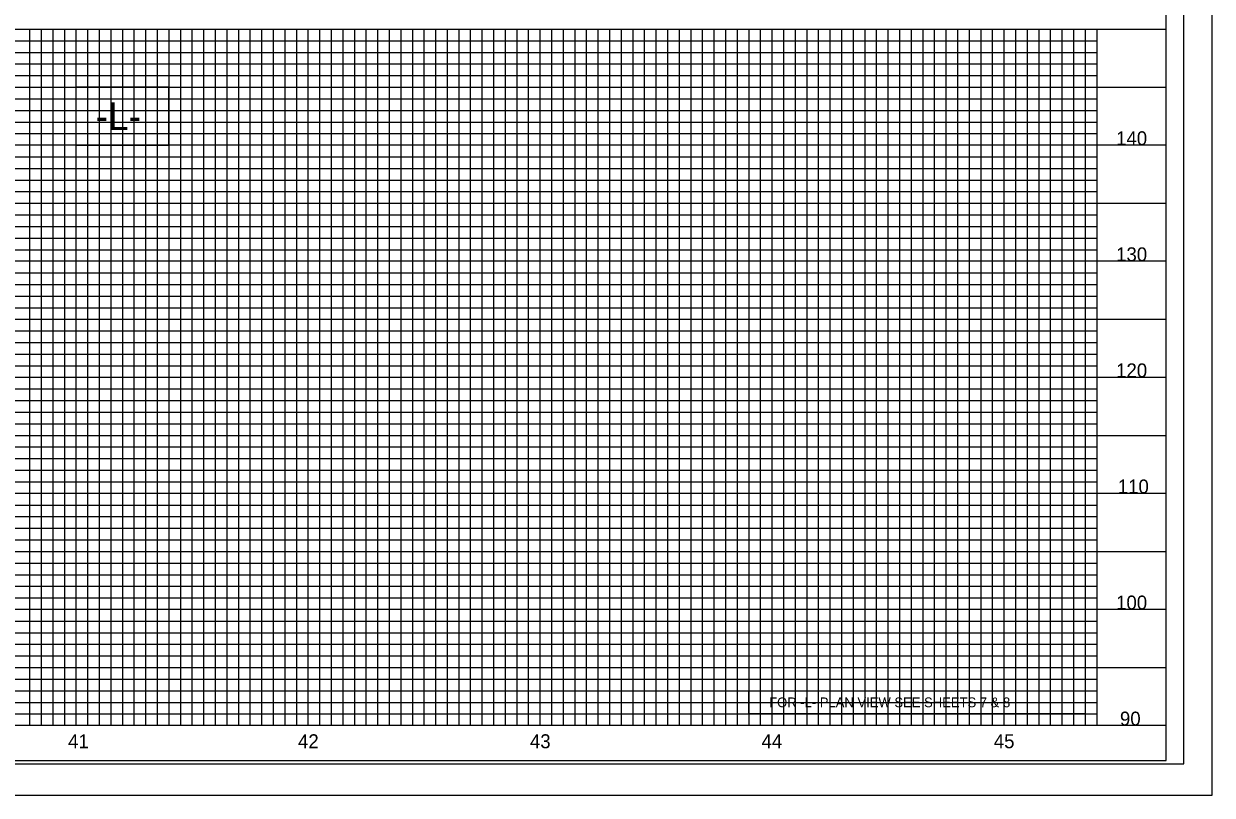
# Model space of a CAD drawing. Extents: x 2113763 to 2114783, y 714280 to 714940.
# Drawn here: x 2114270 to 2114783, y 714280 to 714613 of the extents above; entities that cross this region are included whole.
import ezdxf

# ---------------------------------------------------------------- set-up
doc = ezdxf.new("R2010")
doc.units = 0
for name, color, linetype in [('Exist Vertical Profile Horizontal Axis Label Major', 7, 'Continuous'), ('Exist Vertical Profile Vertical Axis Label', 7, 'Continuous'), ('Prop Grid Mask', 7, 'Continuous'), ('Prop PFL Text', 7, 'Continuous'), ('Sheet Cutting Line CELL', 7, 'Continuous'), ('Sheet Layout Profile Border Port 2', 7, 'Continuous'), ('Sheet Plot Border Inside CELL', 7, 'Continuous'), ('Sheet Plot Border Outside CELL', 7, 'Continuous'), ('Sheet Profile CELL', 7, 'Continuous'), ('Sheet Profile Grid Major CELL', 7, 'Continuous'), ('Sheet Profile Grid Middle CELL', 7, 'Continuous'), ('Sheet Profile Grid Minor CELL', 7, 'Continuous')]:
    doc.layers.add(name, color=color, linetype=linetype)

msp = doc.modelspace()

# ---------------------------------------------------------------- linework, layer by layer
at = {"layer": 'Exist Vertical Profile Vertical Axis Label'}
msp.add_lwpolyline([(2114582.76, 714325.29), (2114727.76, 714325.29), (2114727.76, 714315.29), (2114582.76, 714315.29)], close=True, dxfattribs=at)
at = {"layer": 'Prop Grid Mask'}
for points in [[(2114292.76, 714560.29), (2114332.76, 714560.29), (2114332.76, 714585.29), (2114292.76, 714585.29)], [(2114582.76, 714325.29), (2114727.76, 714325.29), (2114727.76, 714315.29), (2114582.76, 714315.29)]]:
    msp.add_lwpolyline(points, close=True, dxfattribs=at)
at = {"layer": 'Prop PFL Text'}
msp.add_lwpolyline([(2114292.76, 714560.29), (2114332.76, 714560.29), (2114332.76, 714585.29), (2114292.76, 714585.29)], close=True, dxfattribs=at)
at = {"layer": 'Sheet Cutting Line CELL'}
for p, q in [((2114782.56, 714280.29), (2114782.56, 714940.29)), ((2113762.56, 714280.29), (2114782.56, 714280.29))]:
    msp.add_line(p, q, dxfattribs=at)
at = {"layer": 'Sheet Layout Profile Border Port 2'}
msp.add_lwpolyline([(2113892.76, 714610.29), (2114732.76, 714610.29), (2114732.76, 714310.29), (2113892.76, 714310.29)], close=True, dxfattribs=at)
at = {"layer": 'Sheet Plot Border Inside CELL'}
msp.add_lwpolyline([(2113770.36, 714293.76), (2114770.26, 714293.76), (2114770.26, 714926.82), (2113770.36, 714926.82)], close=True, dxfattribs=at)
at = {"layer": 'Sheet Plot Border Outside CELL'}
msp.add_lwpolyline([(2113762.56, 714280.29), (2114782.56, 714280.29), (2114782.56, 714940.29), (2113762.56, 714940.29)], close=True, dxfattribs=at)
at = {"layer": 'Sheet Profile CELL'}
for p, q in [((2113862.76, 714610.29), (2114762.76, 714610.29)), ((2114762.76, 714310.29), (2113862.76, 714310.29)), ((2113862.76, 714295.29), (2114762.76, 714295.29))]:
    msp.add_line(p, q, dxfattribs=at)
msp.add_lwpolyline([(2114762.76, 714925.29), (2113862.76, 714925.29), (2113862.76, 714295.29), (2114762.76, 714295.29)], close=True, dxfattribs=at)
at = {"layer": 'Sheet Profile Grid Major CELL'}
for p, q in [((2114292.76, 714610.29), (2114292.76, 714310.29)), ((2114317.76, 714610.29), (2114317.76, 714310.29)), ((2114342.76, 714610.29), (2114342.76, 714310.29)), ((2114367.76, 714610.29), (2114367.76, 714310.29)), ((2114392.76, 714610.29), (2114392.76, 714310.29)), ((2114417.76, 714610.29), (2114417.76, 714310.29)), ((2114442.76, 714610.29), (2114442.76, 714310.29)), ((2114467.76, 714610.29), (2114467.76, 714310.29)), ((2114492.76, 714610.29), (2114492.76, 714310.29)), ((2114517.76, 714610.29), (2114517.76, 714310.29)), ((2114542.76, 714610.29), (2114542.76, 714310.29)), ((2114567.76, 714610.29), (2114567.76, 714310.29)), ((2114592.76, 714610.29), (2114592.76, 714310.29)), ((2114617.76, 714610.29), (2114617.76, 714310.29)), ((2114642.76, 714610.29), (2114642.76, 714310.29)), ((2114667.76, 714610.29), (2114667.76, 714310.29)), ((2114692.76, 714610.29), (2114692.76, 714310.29)), ((2114717.76, 714610.29), (2114717.76, 714310.29)), ((2114732.76, 714610.29), (2114732.76, 714310.29)), ((2113862.76, 714585.29), (2114762.76, 714585.29)), ((2114762.76, 714560.29), (2113862.76, 714560.29)), ((2113862.76, 714535.29), (2114762.76, 714535.29)), ((2114762.76, 714510.29), (2113862.76, 714510.29)), ((2113862.76, 714485.29), (2114762.76, 714485.29)), ((2114762.76, 714460.29), (2113862.76, 714460.29)), ((2113862.76, 714435.29), (2114762.76, 714435.29)), ((2114762.76, 714410.29), (2113862.76, 714410.29)), ((2113862.76, 714385.29), (2114762.76, 714385.29)), ((2114762.76, 714360.29), (2113862.76, 714360.29)), ((2113862.76, 714335.29), (2114762.76, 714335.29))]:
    msp.add_line(p, q, dxfattribs=at)
at = {"layer": 'Sheet Profile Grid Middle CELL'}
for p, q in [((2113892.76, 714605.29), (2114732.76, 714605.29)), ((2113892.76, 714600.29), (2114732.76, 714600.29)), ((2113892.76, 714595.29), (2114732.76, 714595.29)), ((2113892.76, 714590.29), (2114732.76, 714590.29)), ((2113892.76, 714580.29), (2114732.76, 714580.29)), ((2113892.76, 714575.29), (2114732.76, 714575.29)), ((2113892.76, 714570.29), (2114732.76, 714570.29)), ((2113892.76, 714565.29), (2114732.76, 714565.29)), ((2113892.76, 714555.29), (2114732.76, 714555.29)), ((2113892.76, 714550.29), (2114732.76, 714550.29)), ((2113892.76, 714545.29), (2114732.76, 714545.29)), ((2113892.76, 714540.29), (2114732.76, 714540.29)), ((2113892.76, 714530.29), (2114732.76, 714530.29)), ((2113892.76, 714525.29), (2114732.76, 714525.29)), ((2113892.76, 714520.29), (2114732.76, 714520.29)), ((2113892.76, 714515.29), (2114732.76, 714515.29)), ((2113892.76, 714505.29), (2114732.76, 714505.29)), ((2113892.76, 714500.29), (2114732.76, 714500.29)), ((2113892.76, 714495.29), (2114732.76, 714495.29)), ((2113892.76, 714490.29), (2114732.76, 714490.29)), ((2113892.76, 714480.29), (2114732.76, 714480.29)), ((2113892.76, 714475.29), (2114732.76, 714475.29)), ((2113892.76, 714470.29), (2114732.76, 714470.29)), ((2113892.76, 714465.29), (2114732.76, 714465.29)), ((2113892.76, 714455.29), (2114732.76, 714455.29)), ((2113892.76, 714450.29), (2114732.76, 714450.29)), ((2113892.76, 714445.29), (2114732.76, 714445.29)), ((2113892.76, 714440.29), (2114732.76, 714440.29)), ((2113892.76, 714430.29), (2114732.76, 714430.29)), ((2113892.76, 714425.29), (2114732.76, 714425.29)), ((2113892.76, 714420.29), (2114732.76, 714420.29)), ((2113892.76, 714415.29), (2114732.76, 714415.29)), ((2113892.76, 714405.29), (2114732.76, 714405.29)), ((2113892.76, 714400.29), (2114732.76, 714400.29)), ((2113892.76, 714395.29), (2114732.76, 714395.29)), ((2113892.76, 714390.29), (2114732.76, 714390.29)), ((2113892.76, 714380.29), (2114732.76, 714380.29)), ((2113892.76, 714375.29), (2114732.76, 714375.29)), ((2113892.76, 714370.29), (2114732.76, 714370.29)), ((2113892.76, 714365.29), (2114732.76, 714365.29)), ((2113892.76, 714355.29), (2114732.76, 714355.29)), ((2113892.76, 714350.29), (2114732.76, 714350.29)), ((2113892.76, 714345.29), (2114732.76, 714345.29)), ((2113892.76, 714340.29), (2114732.76, 714340.29)), ((2113892.76, 714330.29), (2114732.76, 714330.29)), ((2113892.76, 714325.29), (2114732.76, 714325.29)), ((2113892.76, 714320.29), (2114732.76, 714320.29)), ((2113892.76, 714315.29), (2114732.76, 714315.29))]:
    msp.add_line(p, q, dxfattribs=at)
msp.add_lwpolyline([(2114657.76, 714475.29), (2114732.76, 714475.29)], dxfattribs=at)
at = {"layer": 'Sheet Profile Grid Minor CELL'}
for p, q in [((2114272.76, 714610.29), (2114272.76, 714310.29)), ((2114277.76, 714610.29), (2114277.76, 714310.29)), ((2114282.76, 714610.29), (2114282.76, 714310.29)), ((2114287.76, 714610.29), (2114287.76, 714310.29)), ((2114297.76, 714610.29), (2114297.76, 714310.29)), ((2114302.76, 714610.29), (2114302.76, 714310.29)), ((2114307.76, 714610.29), (2114307.76, 714310.29)), ((2114312.76, 714610.29), (2114312.76, 714310.29)), ((2114322.76, 714610.29), (2114322.76, 714310.29)), ((2114327.76, 714610.29), (2114327.76, 714310.29)), ((2114332.76, 714610.29), (2114332.76, 714310.29)), ((2114337.76, 714610.29), (2114337.76, 714310.29)), ((2114347.76, 714610.29), (2114347.76, 714310.29)), ((2114352.76, 714610.29), (2114352.76, 714310.29)), ((2114357.76, 714610.29), (2114357.76, 714310.29)), ((2114362.76, 714610.29), (2114362.76, 714310.29)), ((2114372.76, 714610.29), (2114372.76, 714310.29)), ((2114377.76, 714610.29), (2114377.76, 714310.29)), ((2114382.76, 714610.29), (2114382.76, 714310.29)), ((2114387.76, 714610.29), (2114387.76, 714310.29)), ((2114397.76, 714610.29), (2114397.76, 714310.29)), ((2114402.76, 714610.29), (2114402.76, 714310.29)), ((2114407.76, 714610.29), (2114407.76, 714310.29)), ((2114412.76, 714610.29), (2114412.76, 714310.29)), ((2114422.76, 714610.29), (2114422.76, 714310.29)), ((2114427.76, 714610.29), (2114427.76, 714310.29)), ((2114432.76, 714610.29), (2114432.76, 714310.29)), ((2114437.76, 714610.29), (2114437.76, 714310.29)), ((2114447.76, 714610.29), (2114447.76, 714310.29)), ((2114452.76, 714610.29), (2114452.76, 714310.29)), ((2114457.76, 714610.29), (2114457.76, 714310.29)), ((2114462.76, 714610.29), (2114462.76, 714310.29)), ((2114472.76, 714610.29), (2114472.76, 714310.29)), ((2114477.76, 714610.29), (2114477.76, 714310.29)), ((2114482.76, 714610.29), (2114482.76, 714310.29)), ((2114487.76, 714610.29), (2114487.76, 714310.29)), ((2114497.76, 714610.29), (2114497.76, 714310.29)), ((2114502.76, 714610.29), (2114502.76, 714310.29)), ((2114507.76, 714610.29), (2114507.76, 714310.29)), ((2114512.76, 714610.29), (2114512.76, 714310.29)), ((2114522.76, 714610.29), (2114522.76, 714310.29)), ((2114527.76, 714610.29), (2114527.76, 714310.29)), ((2114532.76, 714610.29), (2114532.76, 714310.29)), ((2114537.76, 714610.29), (2114537.76, 714310.29)), ((2114547.76, 714610.29), (2114547.76, 714310.29)), ((2114552.76, 714610.29), (2114552.76, 714310.29)), ((2114557.76, 714610.29), (2114557.76, 714310.29)), ((2114562.76, 714610.29), (2114562.76, 714310.29)), ((2114572.76, 714610.29), (2114572.76, 714310.29)), ((2114577.76, 714610.29), (2114577.76, 714310.29)), ((2114582.76, 714610.29), (2114582.76, 714310.29)), ((2114587.76, 714610.29), (2114587.76, 714310.29)), ((2114597.76, 714610.29), (2114597.76, 714310.29)), ((2114602.76, 714610.29), (2114602.76, 714310.29)), ((2114607.76, 714610.29), (2114607.76, 714310.29)), ((2114612.76, 714610.29), (2114612.76, 714310.29)), ((2114622.76, 714610.29), (2114622.76, 714310.29)), ((2114627.76, 714610.29), (2114627.76, 714310.29)), ((2114632.76, 714610.29), (2114632.76, 714310.29)), ((2114637.76, 714610.29), (2114637.76, 714310.29)), ((2114647.76, 714610.29), (2114647.76, 714310.29)), ((2114652.76, 714610.29), (2114652.76, 714310.29)), ((2114657.76, 714610.29), (2114657.76, 714310.29)), ((2114662.76, 714610.29), (2114662.76, 714310.29)), ((2114672.76, 714610.29), (2114672.76, 714310.29)), ((2114677.76, 714610.29), (2114677.76, 714310.29)), ((2114682.76, 714610.29), (2114682.76, 714310.29)), ((2114687.76, 714610.29), (2114687.76, 714310.29)), ((2114697.76, 714610.29), (2114697.76, 714310.29)), ((2114702.76, 714610.29), (2114702.76, 714310.29)), ((2114707.76, 714610.29), (2114707.76, 714310.29)), ((2114712.76, 714610.29), (2114712.76, 714310.29)), ((2114722.76, 714610.29), (2114722.76, 714310.29)), ((2114727.76, 714610.29), (2114727.76, 714310.29))]:
    msp.add_line(p, q, dxfattribs=at)

# ---------------------------------------------------------------- texts
at = {"layer": 'Exist Vertical Profile Horizontal Axis Label Major'}
for s, p in [('41', (2114289.36, 714300.53)), ('42', (2114388.48, 714300.53)), ('43', (2114488.45, 714300.53)), ('44', (2114588.27, 714300.53)), ('45', (2114688.39, 714300.53))]:
    msp.add_text(s, height=6, dxfattribs=at).set_placement(p)
at = {"layer": 'Exist Vertical Profile Vertical Axis Label'}
for s, p in [('140', (2114741.12, 714560.29)), ('130', (2114741.12, 714510.29)), ('120', (2114741.12, 714460.29)), ('110', (2114741.84, 714410.29)), ('100', (2114741.12, 714360.29)), ('90', (2114742.78, 714310.29))]:
    msp.add_text(s, height=6, dxfattribs=at).set_placement(p)
at = {"layer": 'Prop PFL Text'}
for s, height, p in [('-L-', 12, (2114301.22, 714566.79)), ('FOR -L- PLAN VIEW SEE SHEETS 7 & 8', 4.2, (2114591.56, 714318.19))]:
    msp.add_text(s, height=height, dxfattribs=at).set_placement(p)

doc.saveas('drawing.dxf')
